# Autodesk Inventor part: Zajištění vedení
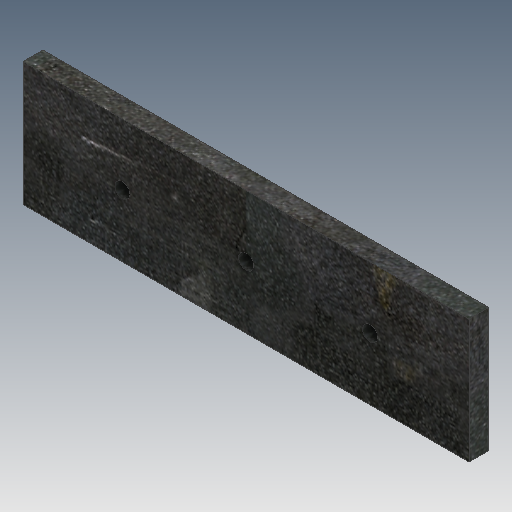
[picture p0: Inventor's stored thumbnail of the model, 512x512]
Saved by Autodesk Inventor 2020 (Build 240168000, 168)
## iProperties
Created: 2025-03
Part Number: Zajištění vedení
Material: Ocel
Document SubType Name: Modeling
Designer: doma
Density: 7.85 g/cm^3
Appearance: Plech
Mass: 559.873 g
Surface Area: 219.627 cm^2
Volume: 71.3214 cm^3
Author: doma
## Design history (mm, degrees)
sketch "Náčrt1"
  geometry: L1 (-90, -25)-(90, -25); L2 (90, -25)-(90, 25); L3 (90, 25)-(-90, 25); L4 (-90, 25)-(-90, -25); L5 (-90, -25)-(90, 25); L6 (90, -25)-(-90, 25); C1 r 3 at (0, 0); C2 r 3 at (-50, 0); C3 r 3 at (50, 0); 1 further point
  constraints: 12 end point, 3 centre point, 2 midpoint, 2 parallel, 1 coincident, 1 horizontal, 1 perpendicular
  dimensions: "d0" = 180 distance of L3.end L2.end; "d1" = 50 distance of L2.end L1.end; "d2" = 6 diameter of C1; "d5" = 6 diameter of C2; "d6" = 6 diameter of C3
extrude "Vysunutí1" new body sketch "Náčrt1" distance "d7" = 8; taper "d8" = 0 deg
node "Těleso1"
